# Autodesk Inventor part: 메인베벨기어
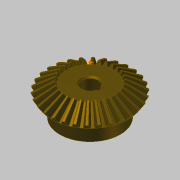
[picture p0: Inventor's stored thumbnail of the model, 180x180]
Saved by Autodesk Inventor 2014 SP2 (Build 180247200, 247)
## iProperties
Created: 2018-09
Part Number: 메인베벨기어
Material: 강철, 탄소
Document SubType Name: Modeling
Categories: <?xml version="1.0" encoding="UTF-16"?> <MemberInstance><Categories><FamilyTemplate><FamilyTemplateParameter ValueType="xs:double" Id="1" ObjectReferenceKey="da
Mass: 290.333 g
Surface Area: 107.709 cm^2
Volume: 36.8911 cm^3
Density: 7.87 g/cm^3
Appearance: 얼룩무늬
CustomPartVersion: 1
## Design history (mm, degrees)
node "맨 위 점"
node "메쉬 평면2"
sketch "톱니 본체 스케치"
  geometry: L1 (0, 0)-(28.669, -21.997); L2 (28.669, -21.997)-(31.109, -18.336); L3 (31.109, -18.336)-(0, 0); L4 (30, -20)-(0, 0); L5 (17.219, -13.212)-(18.685, -11.013); L6 (28.669, -21.997)-(17.219, -13.212); L7 (31.109, -18.336)-(18.685, -11.013); L8 (0, -39.387)-(0, 6.564) reference; L9 (0, -20)-(31.109, -20)
  constraints: 16 end point, 4 point on line, 3 perpendicular, 2 collinear, 1 horizontal alignment, 1 vertical alignment
  dimensions: "d0" = 60 diameter of L4.start L8 (= da_de); "d1" = 57.33744 diameter of L1.end L8 (= da_dfe); "d2" = 62.2188 diameter of L2.end L8 (= da_dae); "d3" = 14.4 distance between parallel lines of L2 L5 (= da_b); "d4" = 18.3359 vertical distance of L2.end L1.start (= da_ve)
revolve "톱니 본체" sketch "톱니 본체 스케치" stored, may be unused: angle "d5" = 90 deg
node "시작점"
node "톱니 평면"
sketch "시작 스케치"
  geometry: L1 (0, -23.505)-(0, 10.645) reference; L2 (-0.709, -2.928)-(0.709, -2.928); A1 r 19.188 centre (-19.457, -7.014) between (-0.709, -2.928) and (-3.232, 3.229); A2 r 19.188 centre (19.457, -7.014) between (3.232, 3.229) and (0.709, -2.928); A3 r 57.403 centre (0, -54.083) between (3.232, 3.229) and (-3.232, 3.229); 1 further point
  constraints: 6 point on circle, 3 centre point, 3 symmetric about line, 2 end point, 1 coincident, 1 perpendicular, 1 other
  dimensions: "d7" = 19.18795 radius of A1 (= fd_rr); "d8" = 19.45712 horizontal distance of point (0, -54.083) A1.centre (= fd_x); "d9" = 47.06905 vertical distance of point (0, -54.083) A1.centre (= fd_y); "d57" = 57.40327 radius of A3 (= 0.5 x fd_dva + 0.3 x da_he); "d58" = 51.15527 distance from line of A3.centre L2 (= 0.5 x fd_dva - 1.12 x da_he)
node "끝점"
  node "끝 평면"
sketch "3D 스케치 오른쪽"
  node "Helical Curve Right" dims "d65" = 229.90621 (computed from da_dm, da_delta, da_beta), "d66" = 31.5, "d67" = 60 (= da_de), "d68" = -9.82794 (= -da_delta), "d69" = 8.10972 (computed from fd_loft, da_delta)
node "끝 평면 오른쪽"
sketch "끝 스케치 오른쪽"
  geometry: L1 (0, -41.54)-(0, 13.178) reference; L2 (-0.422, -1.69)-(0.422, -1.69); A1 r 11.427 centre (-11.587, -4.123) between (-0.422, -1.69) and (-1.925, 1.977); A2 r 11.427 centre (11.587, -4.123) between (1.925, 1.977) and (0.422, -1.69); A3 r 34.184 centre (0, -32.153) between (1.925, 1.977) and (-1.925, 1.977); 1 further point
  constraints: 6 point on circle, 3 centre point, 3 symmetric about line, 2 end point, 1 coincident, 1 perpendicular, 1 other
  dimensions: "d70" = 11.58699 horizontal distance of A3.centre A1.centre (computed from fd_x, fd_ratio); "d71" = 28.03028 vertical distance of point (0, -32.153) A1.centre (computed from fd_y, fd_ratio); "d72" = 11.4267 radius of A1 (computed from fd_rr, fd_ratio); "d73" = 30.46369 distance from line of point (0, -32.153) L2 (computed from d58, fd_ratio); "d74" = 34.18446 radius of A3 (computed from d57, fd_ratio)
feature "로프트 오른쪽" sketch "끝 스케치 오른쪽" dims "d75" = 0, "d77" = 0, "d79" = 0, "d80" = 90 deg, "d85" = 20, "d92" = 90 deg, "d93" = 90 deg, "da_teethtype" = 0 [user parameter]
sketch "3D 스케치 왼쪽"
  node "Helical Curve Left" dims "d26" = 229.90621 (computed from da_dm, da_delta, da_beta), "d27" = 8.10972 (computed from fd_loft, da_delta), "d28" = 60 (= da_de), "d29" = -9.82794 (= -da_delta)
node "끝 평면 왼쪽"
sketch "끝 스케치 왼쪽" dims "d56" = 10.3728 (derived)
  geometry: L1 (0, -43.753)-(0, 15.405) reference; L2 (-0.422, -1.678)-(0.422, -1.678); A1 r 11.427 centre (-11.587, -4.111) between (-0.422, -1.678) and (-1.925, 1.988); A2 r 11.427 centre (11.587, -4.111) between (1.925, 1.988) and (0.422, -1.678); A3 r 34.184 centre (0, -32.142) between (1.925, 1.988) and (-1.925, 1.988); 2 further points; 1 other entity
  constraints: 6 point on circle, 3 centre point, 3 symmetric about line, 2 end point, 1 coincident, 2 other
  dimensions: "d30" = 11.4267 radius of A1 (computed from fd_rr, fd_ratio); "d31" = 11.58699 horizontal distance of point (0, -32.142) A1.centre (computed from fd_x, fd_ratio); "d32" = 28.03028 vertical distance of A1.centre point (0, -32.142) (computed from fd_y, fd_ratio); "d61" = 34.18446 radius of A3 (computed from d57, fd_ratio); "d62" = 30.46369 distance from line of point (0, -32.142) L2 (computed from d58, fd_ratio)
feature "로프트 왼쪽" sketch "끝 스케치 왼쪽" dims "d35" = 0, "d37" = 0, "d39" = 0, "d40" = 90 deg, "d84" = 10, "d90" = 90 deg, "d91" = 90 deg, "da_teethtype" = 0 [user parameter]
sketch "본체 스케치"
  geometry: L1 (0, -35.038)-(0, -19.531) reference; L2 (28.669, -21.997)-(17.219, -13.212) reference; L3 (17.219, -13.212)-(0, -13.212); L4 (28.669, -21.997)-(0, -21.997)
  constraints: 4 end point, 2 perpendicular, 2 point on line
revolve "본체 고정" sketch "본체 스케치" stored, may be unused: angle "d46" = 90 deg
feature "피치 지름" dims angle "d47" = 90 deg
sketch "스케치8"
  geometry: C1 r 22.5 at (0, 0); 1 further point
  constraints: 1 centre point, 1 coincident
  dimensions: "d94" = 45 diameter of C1
extrude "돌출1" join sketch "스케치8" distance "d95" = 13; taper "d96" = 0 deg
sketch "스케치9"
  geometry: 1 further point
hole "구멍1" sketch "스케치9" at (0, 0) diameter "d97" = 12; stored, may be unused: countersink angle "d101" = 90 deg, drill point angle "d103" = 118 deg; dims "d98" = 6, "d99" = 4, "d100" = 2, "d102" = 8
sketch "스케치10"
  geometry: L1 (5.657, 2)-(7.8, 2); L2 (7.8, 2)-(7.8, -2); L3 (7.8, -2)-(5.657, -2); A1 r 6 centre (0, 0) between (5.657, 2) and (5.657, -2) reference; 1 further point
  constraints: 6 end point, 2 parallel, 2 point on circle, 1 horizontal, 1 perpendicular
  dimensions: "d104" = 4 distance of L1.end L2.end; "d112" = 13.8 dimension on A1 L2
extrude "돌출2" cut sketch "스케치10" stored distance "d106" = 10; taper "d107" = 0 deg
chamfer "모따기1" distance "d108" = 1; stored, may be unused: second distance "d109" = 2, angle "d110" = 45 deg
fillet "모깎기1" dims "d111" = 2
body "Solid1"
feature "로프트" dims "d17" = 0, "d18" = 90 deg, "d19" = 0, "d20" = 90 deg, "d89" = 0, "da_teethtype" = 0 [user parameter]
pattern_circular "원형 패턴" dims angle "d22" = 360 deg, "d88" = 0, "da_teethtype" = 0 [user parameter]
pattern_circular "원형 패턴 오른쪽" dims angle "d82" = 360 deg, "da_teethtype" = 0 [user parameter]
pattern_circular "원형 패턴 왼쪽" dims angle "d42" = 360 deg, "da_teethtype" = 0 [user parameter]
sketch "끝 스케치"
  geometry: L1 (0, -15.359)-(0, 6.983) reference; L2 (-0.422, -1.69)-(0.422, -1.69); A1 r 11.427 centre (-11.587, -4.123) between (-0.422, -1.69) and (-1.925, 1.977); A2 r 11.427 centre (11.587, -4.123) between (1.925, 1.977) and (0.422, -1.69); A3 r 34.184 centre (0, -32.153) between (1.925, 1.977) and (-1.925, 1.977); 1 further point
  constraints: 6 point on circle, 3 centre point, 3 symmetric about line, 2 end point, 1 coincident, 1 other
  dimensions: "d12" = 11.4267 radius of A1 (computed from fd_rr, fd_ratio); "d15" = 11.58699 horizontal distance of A1.centre point (0, -32.153) (computed from fd_x, fd_ratio); "d16" = 28.03028 vertical distance of A1.centre point (0, -32.153) (computed from fd_y, fd_ratio); "d59" = 34.18446 radius of A3 (computed from d57, fd_ratio); "d60" = 30.46369 distance from line of A3.centre L2 (computed from d58, fd_ratio)
sketch "Sketch6"
  geometry: L1 (30, -20)-(0, 0) reference; L2 (0, -37.8)-(0, 6.3) reference
body "Srf1"
other parameters: "da_b" = 14.4 [user parameter; used in 2 equation terms], "da_de" = 60 [user parameter; used in 4 equation terms], "da_dae" = 62.2188 [user parameter; used in 2 equation terms], "da_dfe" = 57.33744 [user parameter; used in 1 equation term], "da_le" = 36.05551 [user parameter; used in 1 equation term], "da_omega" = 90 deg [user parameter; used in 1 equation term], "da_beta" = 0 [user parameter; used in 2 equation terms], "da_delta" = 9.82794 [user parameter; used in 8 equation terms], "da_alpha" = 20 deg [user parameter; used in 2 equation terms], "da_he" = 4.4 [user parameter; used in 4 equation terms], "da_ve" = 18.3359 [user parameter; used in 1 equation term], "fd_dv" = 108.16654 (computed from da_de, da_delta) [user parameter; used in 1 equation term], "fd_dva" = 112.16654 (computed from da_dae, da_delta) [user parameter; used in 3 equation terms], "fd_dvb" = 101.6433 (computed from fd_dv, da_alpha) [user parameter; used in 2 equation terms], "da_zv" = 540.83269 [user parameter; used in 1 equation term], "fd_loft" = 14.62 (= da_b + 0.05 x da_he) [user parameter; used in 4 equation terms], "fd_ratio" = 5.95514 (computed from da_le, fd_loft) [user parameter; used in 15 equation terms], "fd_rr" = 19.18795 (computed from fd_dd, fd_dvb) [user parameter; used in 6 equation terms], "fd_angle" = 0.29367 (computed from da_zv) [user parameter; used in 4 equation terms], "fd_x1" = 1.58802 (computed from da_dvw, fd_angle) [user parameter; used in 1 equation term], "fd_y1" = 54.05995 (computed from da_dvw, fd_angle) [user parameter; used in 1 equation term], "fd_x2" = 17.8691 (computed from fd_rr, fd_angle2, fd_angle) [user parameter; used in 1 equation term], "fd_y2" = 6.9909 (computed from fd_rr, fd_angle2, fd_angle) [user parameter; used in 1 equation term], "fd_x" = 19.45712 (= fd_x1 + fd_x2) [user parameter; used in 4 equation terms], "fd_y" = 47.06905 (= fd_y1 - fd_y2) [user parameter; used in 4 equation terms], "fd_angle2" = 3.43555 (computed from fd_dvb, fd_dd, da_alpha) [user parameter; used in 2 equation terms], "fd_dd" = 108.64654 (= fd_dva - 0.8 x da_he) [user parameter; used in 2 equation terms], "da_dvw" = 108.16654 [user parameter; used in 2 equation terms], "d11" = 14.62 (= fd_loft), "da_dm" = 48.01848 [user parameter; used in 2 equation terms], "da_x" = 0 [user parameter], "da_m" = 2 [user parameter], "d48" = 0, "d49" = 0, "d50" = 90 deg (= da_omega), "d51" = 6 deg (computed from da_z), "d52" = 0, "d53" = 0, "d54" = 0
